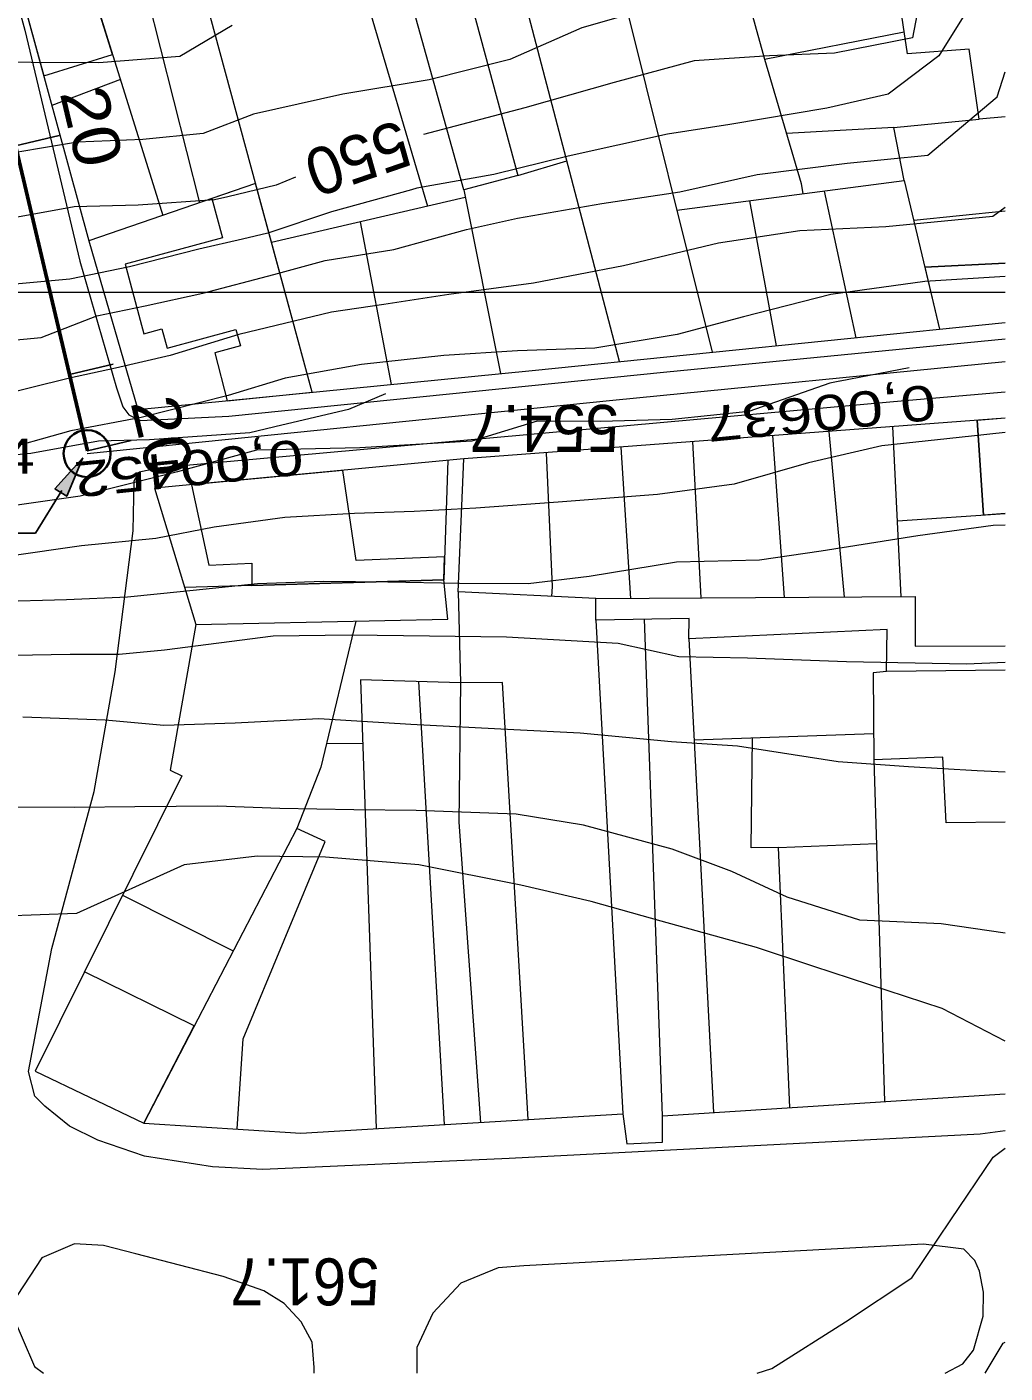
# Model space of a CAD drawing. Extents: x 949 to 2631, y -1701 to -513.
# Drawn here: x 1355.6 to 1439, y -912.7 to -798 of the extents above; entities that cross this region are included whole.
import ezdxf
from ezdxf.enums import TextEntityAlignment as Align

# ---------------------------------------------------------------- set-up
doc = ezdxf.new("R2010")
doc.units = 0
doc.header["$LTSCALE"] = 1.2
for name, color, linetype, lineweight in [('10', 7, 'Continuous', 13), ('11', 7, 'Continuous', 13), ('13', 7, 'Continuous', 35), ('21', 7, 'Continuous', 13), ('29', 7, 'Continuous', 25), ('3', 7, 'Continuous', 13), ('32', 7, 'Continuous', 13), ('33', 7, 'Continuous', 25), ('34', 7, 'Continuous', 35), ('4', 7, 'Continuous', 13), ('5', 7, 'Continuous', 13), ('8', 7, 'Continuous', 13)]:
    doc.layers.add(name, color=color, linetype=linetype, lineweight=lineweight)
doc.layers.add('63', color=7, linetype='Continuous')

msp = doc.modelspace()

# ---------------------------------------------------------------- hatches: boundary and pattern name
at = {"layer": '33'}
msp.add_hatch(color=256, dxfattribs=at).paths.add_polyline_path([(1360.391, -834.707), (1359.02, -837.983), (1358.007, -837.339)])

# ---------------------------------------------------------------- linework, layer by layer
at = {"layer": '10'}
for p, q in [((1392.852, -811.882), (1384.502, -781.892)), ((1402.982, -781.472), (1414.022, -825.712)), ((1380.812, -782.942), (1389.762, -813.272)), ((1379.922, -829.122), (1368.372, -786.452)), ((1370.352, -812.982), (1363.972, -787.702)), ((1359.382, -788.992), (1367.202, -814.062)), ((1418.482, -800.752), (1430.382, -798.432)), ((1363.592, -802.492), (1357.762, -804.692)), ((1429.492, -806.572), (1420.352, -807.092)), ((1375.102, -811.342), (1360.912, -816.232)), ((1430.382, -811.092), (1433.372, -823.752)), ((1392.982, -812.522), (1376.462, -816.362)), ((1417.192, -812.812), (1419.462, -825.162)), ((1423.552, -811.982), (1426.262, -824.472)), ((1438.974, -813.696), (1431.192, -814.502)), ((1432.122, -818.462), (1438.974, -818.119)), ((1423.942, -832.452), (1425.252, -846.572)), ((1430.112, -846.542), (1429.422, -832.042)), ((1436.592, -831.492), (1437.132, -839.582)), ((1413.072, -846.642), (1412.382, -833.322)), ((1419.142, -832.812), (1420.152, -846.602)), ((1406.232, -833.792), (1407.052, -846.682)), ((1429.802, -840.072), (1438.974, -839.458)), ((1404.092, -848.532), (1406.402, -890.602)), ((1409.772, -890.772), (1408.242, -848.462)), ((1412.032, -850.112), (1414.132, -890.482)), ((1389.002, -853.762), (1391.182, -891.502)), ((1412.482, -858.732), (1427.772, -858.202)), ((1381.152, -859.012), (1384.252, -859.042)), ((1363.772, -871.962), (1373.212, -876.692)), ((1369.892, -883.092), (1360.542, -878.482))]:
    msp.add_line(p, q, dxfattribs=at)
for points in [[(1438.974, -805.651), (1436.752, -805.862), (1435.902, -799.902), (1430.662, -800.302), (1427.992, -782.402), (1413.842, -783.082), (1413.852, -784.032), (1409.632, -785.252), (1408.812, -780.982), (1400.862, -781.652), (1399.762, -777.582), (1353.892, -790.552), (1360.912, -816.232), (1365.092, -830.592), (1398.692, -827.262), (1438.974, -823.176)], [(1406.092, -826.512), (1406.122, -826.512), (1393.742, -779.282)], [(1389.302, -780.542), (1397.462, -810.662), (1401.642, -809.412)], [(1413.852, -784.032), (1418.482, -800.752), (1421.602, -811.352), (1421.732, -812.222)], [(1411.012, -813.622), (1430.382, -811.092), (1429.492, -806.572), (1436.752, -805.862)], [(1397.462, -810.662), (1392.852, -811.882), (1395.972, -827.532)], [(1386.682, -828.452), (1386.692, -828.452), (1384.052, -814.602)], [(1438.974, -831.317), (1392.862, -834.802), (1366.492, -837.302), (1370.032, -848.902), (1367.822, -861.312), (1368.832, -861.782), (1356.332, -886.952), (1365.602, -891.372), (1378.972, -892.222), (1406.402, -890.602), (1406.732, -893.132), (1409.792, -892.992), (1409.772, -890.772), (1438.974, -888.873)], [(1399.862, -834.272), (1400.372, -845.662), (1400.332, -846.512)], [(1391.482, -834.932), (1391.162, -845.092), (1369.072, -845.752)], [(1391.222, -843.132), (1383.672, -843.452), (1382.542, -835.782)], [(1404.112, -846.702), (1392.372, -846.132), (1392.862, -834.802)], [(1370.032, -848.902), (1391.482, -848.462), (1391.162, -845.092)], [(1392.372, -846.132), (1392.562, -853.862), (1392.422, -865.752), (1394.262, -891.312)], [(1438.974, -852.794), (1428.872, -852.912), (1428.922, -849.342), (1412.032, -850.112), (1412.052, -848.402), (1404.092, -848.532), (1404.112, -846.702), (1431.302, -846.532), (1431.302, -850.742), (1438.974, -850.712)], [(1383.662, -848.622), (1380.662, -861.052), (1378.612, -866.282), (1365.602, -891.372)], [(1428.872, -852.912), (1427.722, -853.022), (1427.792, -860.432)], [(1392.562, -853.862), (1384.062, -853.612), (1385.382, -891.842)], [(1398.332, -891.072), (1396.162, -853.832), (1392.562, -853.862)], [(1419.662, -867.892), (1417.342, -867.932), (1417.462, -858.562)], [(1438.974, -865.74), (1433.962, -865.812), (1433.662, -860.212), (1427.792, -860.432), (1428.712, -889.542)], [(1373.542, -891.872), (1374.062, -884.202), (1381.042, -867.382), (1378.612, -866.282)], [(1420.642, -890.062), (1419.662, -867.892), (1428.022, -867.562)]]:
    msp.add_lwpolyline(points, dxfattribs=at)
at = {"layer": '11'}
for points in [[(1353.892, -790.552), (1357.072, -802.172), (1362.922, -800.342), (1359.382, -788.992)], [(1379.922, -829.122), (1375.102, -811.342), (1371.392, -812.622), (1372.302, -815.962), (1363.992, -818.212), (1365.592, -824.152), (1367.132, -823.732), (1367.572, -825.362), (1373.442, -823.772), (1373.822, -825.172), (1371.632, -825.772), (1372.702, -829.842)], [(1369.642, -837.002), (1371.132, -843.862), (1374.792, -843.672), (1374.782, -845.582), (1391.162, -845.092), (1391.222, -843.132), (1383.672, -843.452), (1382.542, -835.782)], [(1356.332, -886.952), (1365.602, -891.372), (1369.892, -883.092), (1360.542, -878.482)]]:
    msp.add_lwpolyline(points, close=True, dxfattribs=at)
for points in [[(1438.974, -818.119), (1432.122, -818.462), (1433.372, -823.752), (1438.974, -823.179)], [(1438.974, -839.456), (1437.132, -839.582), (1436.592, -831.492), (1438.974, -831.313)]]:
    msp.add_lwpolyline(points, dxfattribs=at)
at = {"layer": '21'}
msp.add_line((1438.974, -820.632), (1228.032, -820.632), dxfattribs=at)
at = {"layer": '29'}
for p, q in [((1354.651, -808.143), (1358.377, -807.261)), ((1359.254, -827.606), (1362.981, -826.724))]:
    msp.add_line(p, q, dxfattribs=at)
at = {"layer": '29', "lineweight": 53}
msp.add_lwpolyline([(1073.88, -805.132), (1073.202, -806.436), (1075.81, -807.79), (1086.799, -786.637), (1101.557, -787.729), (1138.256, -763.647), (1228.052, -719.585), (1284.057, -691.479), (1304.502, -688.949), (1348.513, -782.198), (1360.795, -834.118)], dxfattribs=at)
at = {"layer": '29'}
msp.add_lwpolyline([(1086.799, -786.637), (1101.557, -787.729), (1138.256, -763.647), (1228.052, -719.585), (1284.057, -691.479), (1304.502, -688.949), (1348.513, -782.198), (1360.795, -834.118), (1364.521, -833.237)], dxfattribs=at)
at = {"layer": '32'}
msp.add_lwpolyline([(1360.751, -834.347), (1405.561, -829.787), (1438.974, -826.499)], dxfattribs=at)
at = {"layer": '33'}
for p, q in [((1358.611, -837.478), (1356.371, -841.118)), ((1356.371, -841.118), (1338.63, -841.118))]:
    msp.add_line(p, q, dxfattribs=at)
msp.add_lwpolyline([(1360.391, -834.707), (1359.02, -837.983), (1358.007, -837.339)], close=True, dxfattribs=at)
at = {"layer": '33', "lineweight": 35}
msp.add_circle((1360.751, -834.347), 2, dxfattribs=at)
at = {"layer": '4'}
for points in [[(1438.974, -766.001), (1435.942, -766.492), (1433.562, -771.642), (1432.732, -776.712), (1432.682, -783.502), (1432.622, -788.752), (1431.632, -796.132), (1431.092, -798.932), (1424.442, -800.232), (1418.892, -800.472), (1412.482, -800.882), (1405.672, -802.742), (1398.042, -804.902), (1389.412, -807.172)], [(1378.512, -810.802), (1376.852, -811.492), (1372.742, -812.462), (1371.602, -812.732), (1365.112, -813.192), (1359.652, -813.332), (1353.232, -814.502), (1346.912, -815.092), (1340.882, -816.492), (1335.632, -818.862), (1330.042, -820.902), (1324.622, -822.252), (1318.182, -823.782), (1311.642, -825.812), (1305.142, -827.332), (1298.702, -830.042), (1293.182, -832.152), (1288.132, -834.362), (1282.492, -836.142), (1275.742, -839.122), (1271.452, -841.772), (1267.422, -845.862), (1262.442, -849.192)], [(1430.802, -827.032), (1424.912, -828.172), (1424.892, -828.172), (1424.042, -828.342), (1417.142, -830.762), (1410.602, -831.452), (1404.502, -831.602), (1399.112, -831.572), (1393.532, -833.292), (1384.002, -833.862), (1375.192, -834.062), (1368.462, -835.902), (1360.162, -837.972), (1354.212, -838.822)], [(1386.188, -829.27), (1383.028, -830.583), (1377.343, -831.925), (1374.633, -832.567), (1366.076, -833.173), (1361.713, -833.285), (1355.959, -834.334), (1350.117, -834.879)], [(1438.974, -875.19), (1433.532, -874.392), (1426.592, -874.082), (1420.412, -872.122), (1415.692, -869.952), (1410.612, -868.052), (1403.052, -865.992), (1397.322, -865.062), (1388.802, -864.752), (1383.492, -864.692), (1377.182, -864.592), (1371.852, -864.372), (1364.832, -864.442), (1359.682, -864.482), (1352.432, -864.472)], [(1437.285, -912.671), (1438.812, -910.112), (1438.974, -910.051)]]:
    msp.add_lwpolyline(points, dxfattribs=at)
at = {"layer": '5'}
for points in [[(1436.262, -795.792), (1433.322, -800.452), (1429.002, -803.742), (1423.782, -804.932), (1415.512, -806.322), (1410.202, -807.142), (1401.752, -809.012), (1395.402, -810.572), (1388.852, -811.742), (1388.402, -811.872), (1381.572, -813.762), (1376.142, -815.572), (1374.002, -816.072), (1370.262, -816.932), (1364.372, -818.442), (1359.282, -819.482), (1349.352, -820.392)], [(1409.772, -796.122), (1402.902, -798.082), (1396.772, -800.782), (1389.892, -802.502), (1382.532, -803.722), (1374.932, -805.442), (1370.652, -807.082), (1365.512, -807.582), (1359.942, -807.822), (1352.102, -809.122)], [(1373.102, -797.892), (1368.652, -800.522), (1361.762, -801.052), (1355.992, -801.032), (1348.812, -800.982), (1342.002, -803.242), (1333.392, -805.722), (1325.082, -807.412), (1317.142, -809.692), (1310.312, -812.552), (1304.182, -815.082), (1295.672, -817.222), (1290.022, -820.902), (1283.402, -824.092), (1278.002, -826.792), (1273.092, -828.752), (1268.922, -831.942), (1265.482, -836.612)], [(1351.392, -824.962), (1356.852, -824.452), (1361.572, -822.622), (1365.712, -821.752), (1370.612, -820.682), (1376.672, -819.082), (1381.032, -817.912), (1386.892, -816.962), (1393.082, -815.262), (1397.422, -814.302), (1404.622, -813.052), (1411.252, -812.062), (1417.852, -810.572), (1425.512, -809.612), (1432.382, -808.912), (1438.292, -803.962), (1438.974, -801.827)], [(1438.974, -813.373), (1437.942, -814.162), (1428.812, -815.042), (1421.472, -815.362), (1414.552, -816.422), (1406.472, -818.342), (1398.802, -819.832), (1391.572, -820.792), (1386.032, -821.642), (1381.582, -822.302), (1373.692, -824.192), (1367.842, -826.002), (1363.162, -827.072), (1359.262, -827.932), (1352.582, -829.562)], [(1438.974, -819.25), (1432.132, -819.682), (1424.132, -820.792), (1416.682, -822.702), (1411.042, -824.192), (1404.022, -825.362), (1397.422, -825.582), (1391.142, -826.002), (1384.122, -826.752), (1377.632, -827.922), (1372.772, -829.392), (1365.352, -831.272), (1359.362, -832.422), (1352.652, -834.282)], [(1438.974, -832.551), (1436.112, -832.852), (1428.472, -833.682), (1422.222, -835.132), (1415.902, -836.952), (1409.352, -837.842), (1400.902, -838.482), (1393.872, -838.982), (1388.632, -839.282), (1383.532, -839.452), (1377.602, -839.782), (1371.592, -840.612), (1366.602, -841.582), (1360.282, -842.202), (1354.132, -843.082)], [(1438.974, -840.433), (1437.962, -840.482), (1431.552, -841.342), (1423.312, -842.652), (1418.042, -843.432), (1410.972, -843.602), (1403.532, -844.812), (1398.342, -845.442), (1392.492, -845.422), (1386.392, -845.302), (1380.912, -845.232), (1375.262, -845.452), (1368.982, -846.082), (1364.192, -846.582), (1359.012, -846.792), (1352.812, -846.972)], [(1438.974, -852.146), (1435.682, -852.292), (1425.472, -852.072), (1417.032, -851.762), (1411.182, -851.672), (1406.012, -850.532), (1396.502, -849.992), (1389.942, -849.912), (1383.242, -849.822), (1376.612, -849.892), (1367.362, -851.092), (1363.482, -851.452), (1359.322, -851.452), (1354.472, -851.532)], [(1438.974, -861.488), (1436.602, -861.362), (1430.732, -861.042), (1424.742, -860.612), (1416.172, -859.262), (1410.542, -858.912), (1402.762, -858.152), (1397.122, -857.882), (1388.352, -857.422), (1380.492, -856.952), (1373.362, -857.302), (1367.292, -857.512), (1362.292, -857.042), (1355.282, -856.802)], [(1438.974, -884.394), (1433.602, -881.622), (1422.692, -878.042), (1417.792, -876.432), (1409.672, -874.162), (1403.702, -872.502), (1397.722, -871.112), (1389.032, -869.382), (1381.082, -868.732), (1375.252, -868.652), (1369.022, -869.382), (1359.862, -873.512), (1353.672, -873.752), (1351.322, -878.292), (1348.722, -885.022), (1346.842, -890.362), (1346.622, -895.952), (1351.142, -902.512), (1354.172, -907.222), (1356.262, -912.122), (1357.054, -912.671)], [(1417.841, -912.671), (1419.102, -912.282), (1425.382, -908.292), (1431.042, -904.562), (1434.362, -899.622), (1437.972, -894.282), (1438.974, -893.502)]]:
    msp.add_lwpolyline(points, dxfattribs=at)
at = {"layer": '8'}
for points in [[(1336.322, -745.502), (1347.332, -772.682), (1349.352, -777.042), (1350.432, -778.482), (1351.772, -779.272), (1353.892, -779.292), (1389.292, -768.962), (1393.382, -768.602), (1397.262, -768.472), (1399.172, -775.642), (1366.552, -784.062), (1353.192, -789.082), (1353.182, -790.002), (1355.462, -798.272), (1360.132, -817.952), (1363.272, -828.742), (1363.812, -830.352), (1364.322, -831.052), (1365.312, -831.522), (1372.842, -831.172), (1410.152, -827.372), (1438.974, -824.574)], [(1355.752, -886.992), (1357.762, -876.502), (1361.362, -863.122), (1363.142, -852.932), (1364.682, -840.932), (1364.762, -836.672), (1365.182, -835.902), (1366.972, -835.542), (1429.472, -829.922), (1438.974, -829.073)], [(1438.974, -892.03), (1436.842, -892.332), (1396.712, -894.392), (1375.742, -895.322), (1371.452, -895.112), (1365.642, -894.182), (1361.682, -892.832), (1359.242, -891.632), (1357.142, -889.922), (1356.312, -889.072), (1355.752, -886.992)], [(1380.107, -912.671), (1380.112, -912.192), (1379.932, -910.042), (1378.982, -908.302), (1377.552, -906.752), (1375.822, -905.662), (1372.362, -904.442), (1364.912, -902.522), (1362.162, -901.792), (1359.682, -901.662), (1356.892, -902.862), (1354.312, -906.812), (1353.946, -912.671)], [(1433.873, -912.671), (1435.362, -911.892), (1436.292, -910.732), (1437.112, -907.832), (1437.142, -905.792), (1436.802, -904.002), (1436.402, -903.072), (1435.472, -902.122), (1432.032, -901.692), (1397.982, -903.522), (1395.782, -903.692), (1392.602, -905.012), (1390.202, -907.562), (1388.862, -910.502), (1388.838, -912.671)]]:
    msp.add_lwpolyline(points, dxfattribs=at)

# ---------------------------------------------------------------- texts
at = {"layer": '13'}
msp.add_text('550', height=4, rotation=199, dxfattribs=at).set_placement((1387.392, -805.862))
at = {"layer": '3', "width": 0.95}
for s, p in [('554.7', (1406.062, -830.202)), ('561.7', (1385.662, -902.902))]:
    msp.add_text(s, height=4, rotation=180, dxfattribs=at).set_placement(p)
at = {"layer": '33', "width": 1.25}
msp.add_text('PV-244', height=3, dxfattribs=at).set_placement((1339.556, -836.067))
at = {"layer": '34', "width": 1.35}
for s, rotation, p in [('0,00637', 185.62, (1432.9, -828.459)), ('0,00452', 185.811, (1379.012, -833.126))]:
    msp.add_text(s, height=3, rotation=rotation, dxfattribs=at).set_placement(p)
at = {"layer": '63', "width": 1.15}
for p in [(1359.199, -806.935), (1365.228, -833.312)]:
    msp.add_text('20', height=4, rotation=283.309, dxfattribs=at).set_placement(p, align=Align.CENTER)

doc.saveas('drawing.dxf')
